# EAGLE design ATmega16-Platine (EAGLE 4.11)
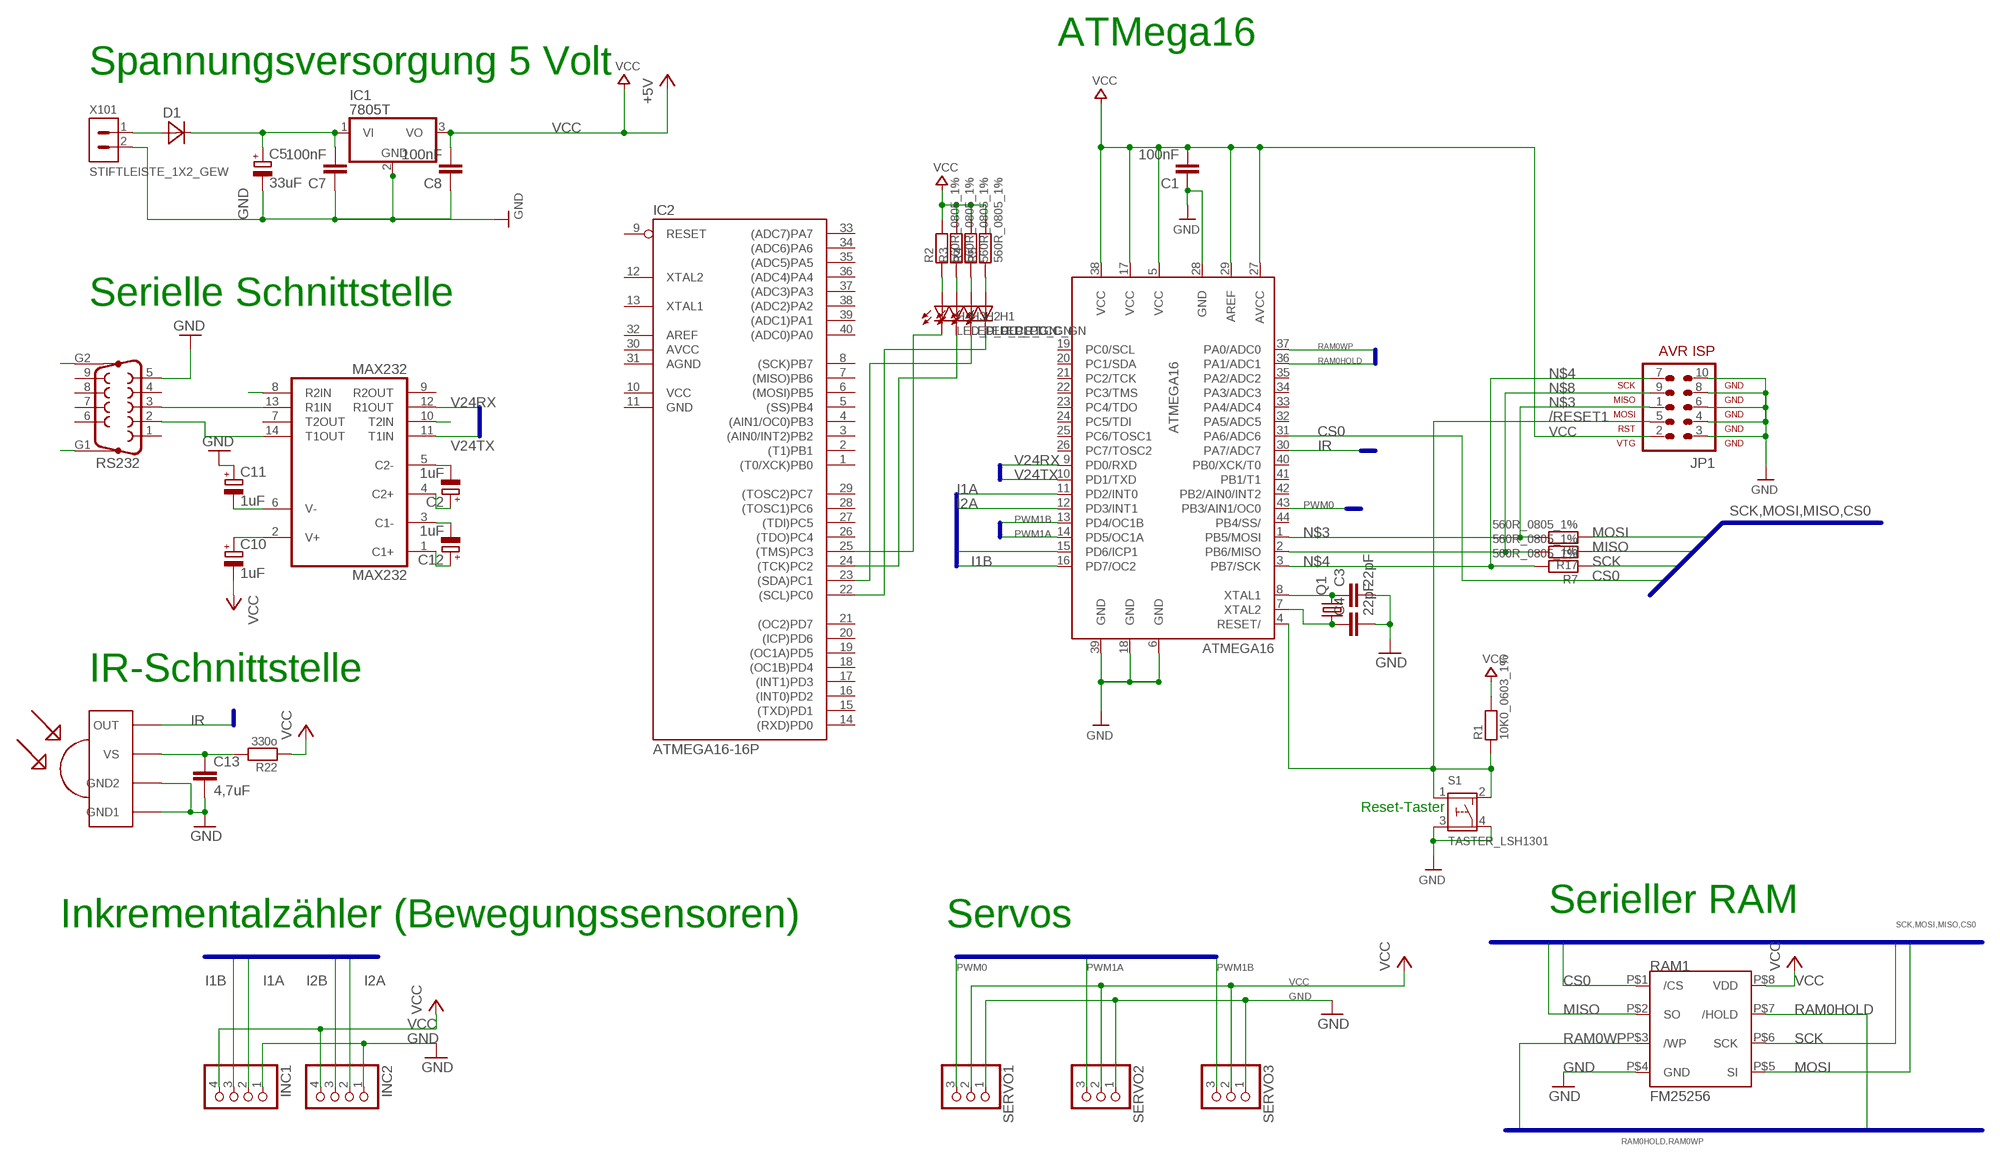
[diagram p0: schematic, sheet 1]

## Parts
ATMEGA16  ATMEGA16  [SQFP-S-10X10-44]
C1  100nF  C2.5/2  [C2.5-2]
C2  1uF  CPOL-EUE2.5-5  [E2,5-5]
C3  22pF  C2.5/2  [C2.5-2]
C4  22pF  C2.5/2  [C2.5-2]
C5  33uF  CPOL-EUE2.5-5  [E2,5-5]
C7  100nF  C2.5/2  [C2.5-2]
C8  100nF  C2.5/2  [C2.5-2]
C10  1uF  CPOL-EUE2.5-5  [E2,5-5]
C11  1uF  CPOL-EUE2.5-5  [E2,5-5]
C12  1uF  CPOL-EUE2.5-5  [E2,5-5]
C13  4,7uF  C-EU025-024X044  [C025-024X044]
D1  DIODE-10  [D-10]
H1  LED_PLCC_GN  [PLCC2]
H2  LED_PLCC_GN  [PLCC2]
H3  LED_PLCC_GN  [PLCC2]
H4  LED_PLCC_RT  [PLCC2]
IC1  7805T  [TO220H]
IC2  ATMEGA16-16P  [DIL40]
INC1  PINHD-1X4  [1X04]
INC2  PINHD-1X4  [1X04]
JP1  AVR-ISP-10  [AVR-ISP-10]
MAX232  MAX232  [DIL16]
Q1  CRYTALHC49S  [HC49/S]
R1  10K0_0603_1%  [R0603]
R2  560R_0805_1%  [R0805]
R3  560R_0805_1%  [R0805]
R4  560R_0805_1%  [R0805]
R5  560R_0805_1%  [R0805]
R6  560R_0805_1%  [R0805]
R7  560R_0805_1%  [R0805]
R17  560R_0805_1%  [R0805]
R22  330o  10K0_0603_1%  [R0603]
RAM1  FM25256  [EIAJ-SOIC-8]
RS232  F09HP  [F09HP]
S1  TASTER_LSH1301  [LSH1301]
SERVO1  PINHD-1X3  [1X03]
SERVO2  PINHD-1X3  [1X03]
SERVO3  PINHD-1X3  [1X03]
TSOP6236  TSOP6236  [TSOP62XX]
X101  STIFTLEISTE_1X2_GEW  [PFOSTENSTECKER_1X2_GEW]

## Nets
/RESET1: ATMEGA16.4(RESET/) JP1.5 R1.1 S1.1 S1.2
CS0: ATMEGA16.31(PA6/ADC6) RAM1.P$1(/CS)
GND: ATMEGA16.6(GND) ATMEGA16.18(GND) ATMEGA16.28(GND) ATMEGA16.39(GND) C1.1 C3.2 C4.2 C5.- C7.1 C8.1 C11.+ C13.2 IC1.2(GND) INC1.1 INC2.1 JP1.3 JP1.4 JP1.6 JP1.8 JP1.10 MAX232.8(R2IN) MAX232.10(T2IN) RAM1.P$4(GND) RS232.5 RS232.G1 RS232.G2 S1.3 S1.4 SERVO1.1 SERVO2.1 SERVO3.1 TSOP6236.GND1 TSOP6236.GND2 X101.2
I1A: ATMEGA16.11(PD2/INT0) INC1.2
I1B: ATMEGA16.16(PD7/OC2) INC1.3
I2A: ATMEGA16.12(PD3/INT1) INC2.2
I2B: INC2.3
IR: ATMEGA16.30(PA7/ADC7) TSOP6236.OUT
MISO: R17.1 RAM1.P$2(SO)
MOSI: R6.1 RAM1.P$5(SI)
N$1: ATMEGA16.8(XTAL1) C3.1 Q1.2
N$2: ATMEGA16.7(XTAL2) C4.1 Q1.1
N$3: ATMEGA16.1(PB5/MOSI) JP1.1 R6.2
N$4: ATMEGA16.3(PB7/SCK) JP1.7 R7.2
N$5: H4.K IC2.25((TMS)PC3)
N$6: ATMEGA16.15(PD6/ICP1)
N$8: ATMEGA16.2(PB6/MISO) JP1.9 R17.2
N$9: D1.1(A) X101.1
N$11: H1.A(A1) R5.1
N$12: C5.+ C7.2 D1.2(K) IC1.1(VI)
N$13: H2.A(A1) R4.1
N$19: H3.A(A1) R3.1
N$20: H4.A(A1) R2.1
N$21: H1.K IC2.22((SCL)PC0)
N$22: H2.K IC2.23((SDA)PC1)
N$23: H3.K IC2.24((TCK)PC2)
N$29: C2.- MAX232.5(C2-)
N$30: C2.+ MAX232.4(C2+)
N$31: C12.- MAX232.3(C1-)
N$32: C12.+ MAX232.1(C1+)
N$33: C11.- MAX232.6(V-)
N$34: C10.+ MAX232.2(V+)
N$40: MAX232.14(T1OUT) RS232.2
N$41: MAX232.13(R1IN) RS232.3
N$49: C13.1 R22.2 TSOP6236.VS
PWM0: ATMEGA16.43(PB3/AIN1/OC0) SERVO1.3
PWM1A: ATMEGA16.14(PD5/OC1A) SERVO2.3
PWM1B: ATMEGA16.13(PD4/OC1B) SERVO3.3
RAM0HOLD: ATMEGA16.36(PA1/ADC1) RAM1.P$7(/HOLD)
RAM0WP: ATMEGA16.37(PA0/ADC0) RAM1.P$3(/WP)
SCK: R7.1 RAM1.P$6(SCK)
V24RX: ATMEGA16.9(PD0/RXD) MAX232.12(R1OUT)
V24TX: ATMEGA16.10(PD1/TXD) MAX232.11(T1IN)
VCC: ATMEGA16.5(VCC) ATMEGA16.17(VCC) ATMEGA16.27(AVCC) ATMEGA16.29(AREF) ATMEGA16.38(VCC) C1.2 C8.2 C10.- IC1.3(VO) INC1.4 INC2.4 JP1.2 R1.2 R2.2 R3.2 R4.2 R5.2 R22.1 RAM1.P$8(VDD) SERVO1.2 SERVO2.2 SERVO3.2 ; supply symbol labelled +5V
Unconnected: ATMEGA16.19(PC0/SCL) ATMEGA16.20(PC1/SDA) ATMEGA16.21(PC2/TCK) ATMEGA16.22(PC3/TMS) ATMEGA16.23(PC4/TDO) ATMEGA16.24(PC5/TDI) ATMEGA16.25(PC6/TOSC1) ATMEGA16.26(PC7/TOSC2) ATMEGA16.32(PA5/ADC5) ATMEGA16.33(PA4/ADC4) ATMEGA16.34(PA3/ADC3) ATMEGA16.35(PA2/ADC2) ATMEGA16.40(PB0/XCK/T0) ATMEGA16.41(PB1/T1) ATMEGA16.42(PB2/AIN0/INT2) ATMEGA16.44(PB4/SS/) IC2.1((T0/XCK)PB0) IC2.2((T1)PB1) IC2.3((AIN0/INT2)PB2) IC2.4((AIN1/OC0)PB3) IC2.5((SS)PB4) IC2.6((MOSI)PB5) IC2.7((MISO)PB6) IC2.8((SCK)PB7) IC2.9(RESET) IC2.12(XTAL2) IC2.13(XTAL1) IC2.14((RXD)PD0) IC2.15((TXD)PD1) IC2.16((INT0)PD2) IC2.17((INT1)PD3) IC2.18((OC1B)PD4) IC2.19((OC1A)PD5) IC2.20((ICP)PD6) IC2.21((OC2)PD7) IC2.26((TDO)PC4) IC2.27((TDI)PC5) IC2.28((TOSC1)PC6) IC2.29((TOSC2)PC7) IC2.33((ADC7)PA7) IC2.34((ADC6)PA6) IC2.35((ADC5)PA5) IC2.36((ADC4)PA4) IC2.37((ADC3)PA3) IC2.38((ADC2)PA2) IC2.39((ADC1)PA1) IC2.40((ADC0)PA0) MAX232.7(T2OUT) MAX232.9(R2OUT) RS232.1 RS232.4 RS232.6 RS232.7 RS232.8 RS232.9

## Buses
SCK,MOSI,MISO,CS0
IR
PWM0,PWM1A,PWM1B
V24RX,V24TX
I1A,I1B,I2A,I2B
RAM0HOLD,RAM0WP

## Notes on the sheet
- ATMega16
- Spannungsversorgung 5 Volt
- Serielle Schnittstelle
- IR-Schnittstelle
- Reset-Taster
- Servos
- Serieller RAM
- Inkrementalzähler (Bewegungssensoren)

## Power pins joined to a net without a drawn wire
AGND: IC2.31(AGND)
AREF: IC2.32(AREF)
AVCC: IC2.30(AVCC)
GND: IC2.11(GND) MAX232.15(GND)
VCC: IC2.10(VCC) MAX232.16(VCC)

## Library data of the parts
ATMEGA16 = IntegrierteSchaltkreise:ATMEGA16: xxxxxxxx
C1 C3 C4 C7 C8 = capacitor-wima:C: CAPACITOR
C2 C5 C10-C12 = rcl:CPOL-EU: POLARIZED CAPACITOR, European symbol
C13 = rcl:C-EU: CAPACITOR, European symbol
D1 = discrete:DIODE-10
H1-H3 = LED:LED_PLCC_GN: 10800036
H4 = LED:LED_PLCC_RT: 10800053
IC1 = linear:78*: Positive VOLTAGE REGULATOR
IC2 = avr:ATMEGA16*P: MICROCONTROLLER 16 Kbytes FLASH 1 kbytes SRAM 512 bytes EEPROM USART 8-channel 10 bit ADC
INC1 INC2 = pinhead:PINHD-1X4: PIN HEADER
JP1 = atmel_3:AVR-ISP-10: AVR ISP-10 Serial Programming Header
MAX232 = maxim:MAX232: RS232 TRANSEIVER
Q1 = crystal:CRYTAL: CRYSTAL
R1 R22 = Widerstände:10K0_0603_1%: 10000534
R2-R7 R17 = Widerstände:560R_0805_1%: 10000417
RAM1 = ramtron25xx:FM25256
RS232 = con-subd:F09HP: SUB-D
S1 = Schalter_Taster:TASTER_LSH1301: 11100014
SERVO1-SERVO3 = pinhead:PINHD-1X3: PIN HEADER
TSOP6236 = tsop_2:TSOP6236
X101 = Stecker_Klemmen:STIFTLEISTE_1X2_GEW: 20900248

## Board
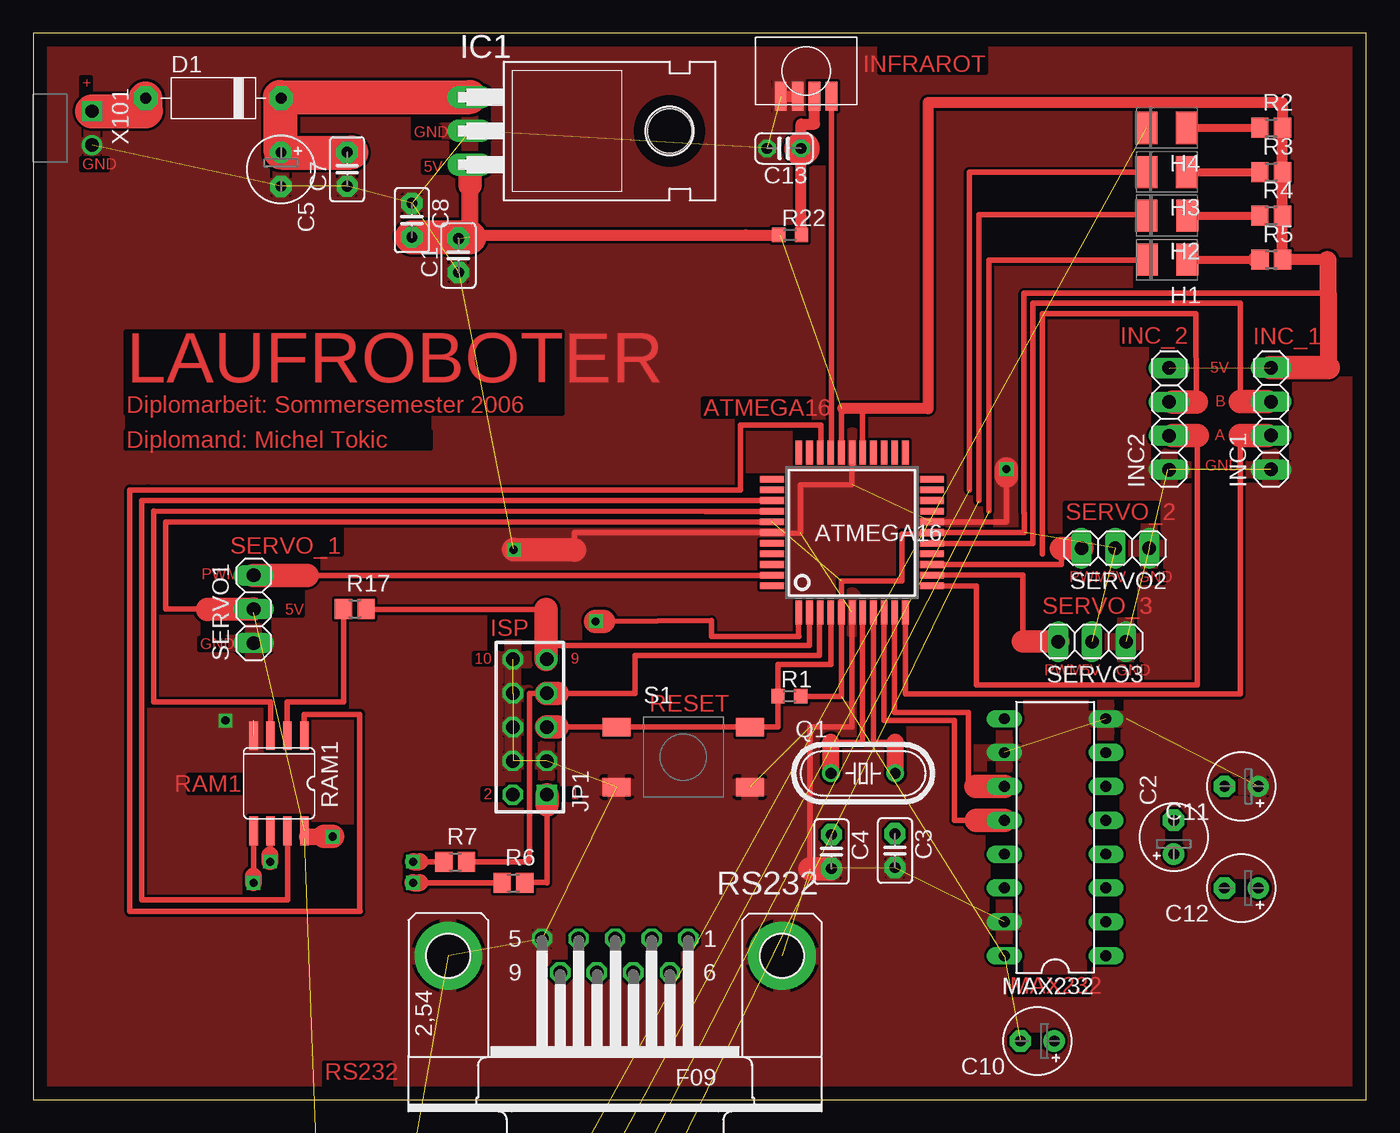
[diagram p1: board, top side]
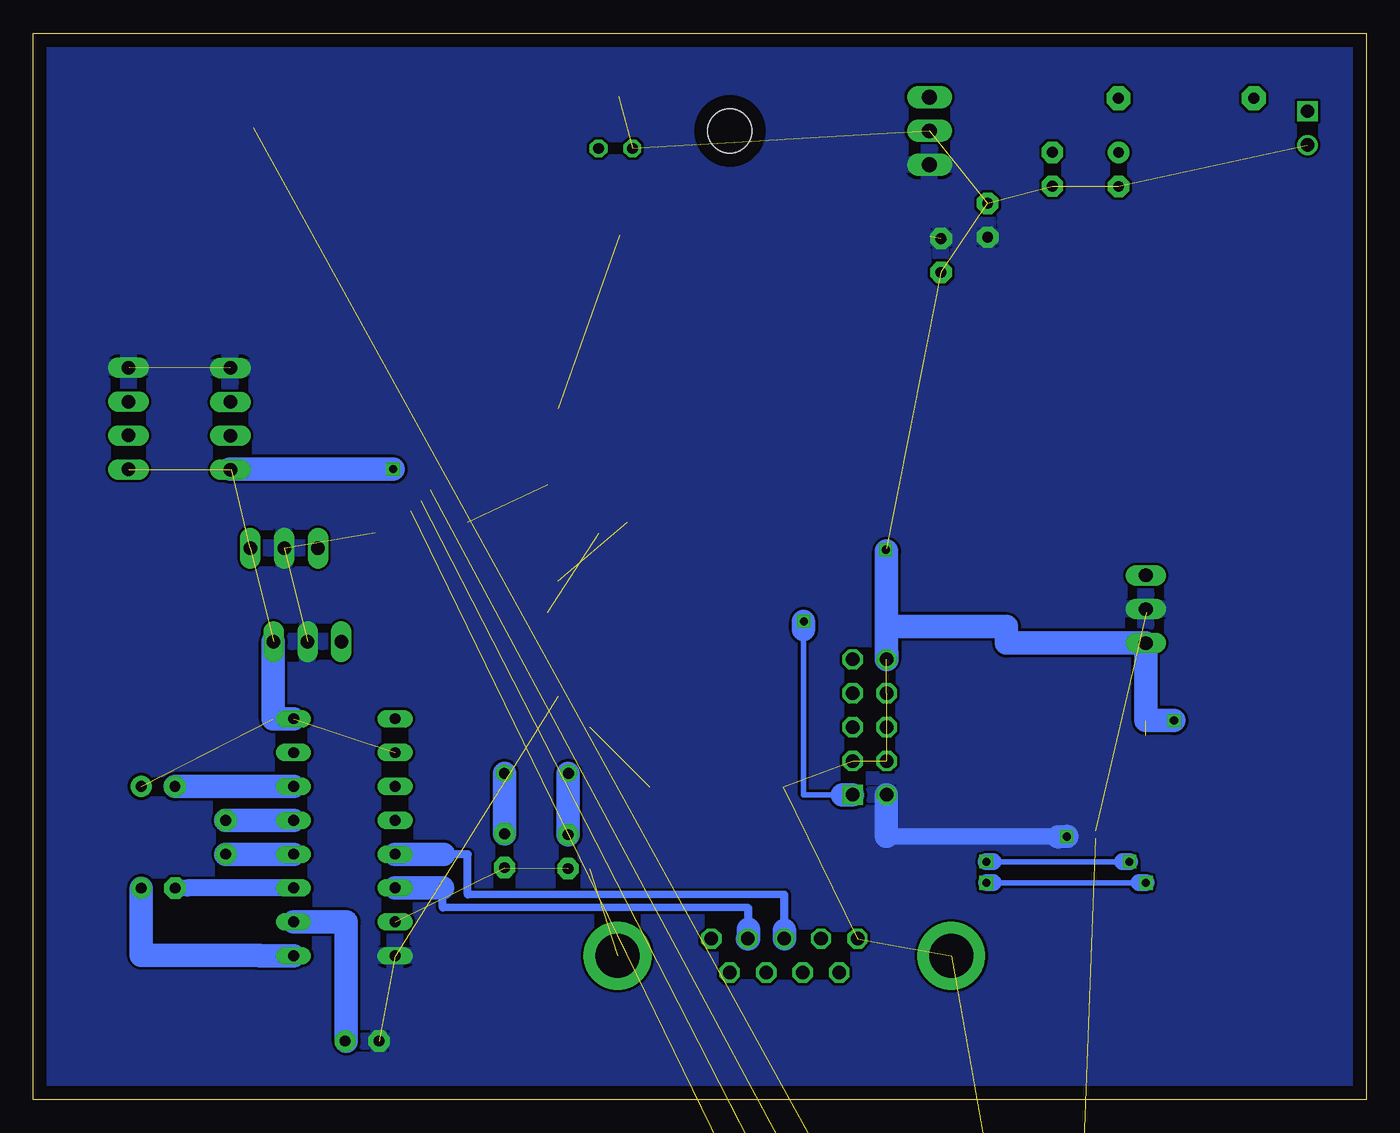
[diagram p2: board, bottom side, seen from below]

Size 100 x 80 mm. Coordinates in mm from the lower left corner, seen from the top.
Outline: 0,0 100,0 100,80 0,80 0,0
Copper layers (1*16): Top 0.035mm / dielectric 1.5mm / Bottom 0.035mm
Design rules "default": minimum track width 10mil, minimum drill 24mil, track to track 8mil, track to pad 8mil, pad to pad 8mil, via to via 8mil, smd to smd 8mil, copper to edge 40mil, drill to drill 8mil, minimum pad ring 10mil, minimum via ring 8mil, stop-mask expansion 4mil, vias tented up to drill 0mil, thermal gap 10mil

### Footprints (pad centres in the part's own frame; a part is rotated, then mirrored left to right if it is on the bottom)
SQFP-S-10X10-44 = smd 0.5 x 1.8: 1 -4,-6; 2 -3.2,-6; 3 -2.4,-6; 4 -1.6,-6; 5 -0.8,-6; 6 0,-6; 7 0.8,-6; 8 1.6,-6; 9 2.4,-6; 10 3.2,-6; 11 4,-6; 23 4,6; 24 3.2,6; 25 2.4,6; 26 1.6,6; 27 0.8,6; 28 0,6; 29 -0.8,6; 30 -1.6,6; 31 -2.4,6; 32 -3.2,6; 33 -4,6 | smd 1.8 x 0.5: 12 6,-4; 13 6,-3.2; 14 6,-2.4; 15 6,-1.6; 16 6,-0.8; 17 6,0; 18 6,0.8; 19 6,1.6; 20 6,2.4; 21 6,3.2; 22 6,4; 34 -6,4; 35 -6,3.2; 36 -6,2.4; 37 -6,1.6; 38 -6,0.8; 39 -6,0; 40 -6,-0.8; 41 -6,-1.6; 42 -6,-2.4; 43 -6,-3.2; 44 -6,-4
C2.5-2 = drill 0.813 pad 1.6 octagon: 1 -1.27,0; 2 1.27,0
E2,5-5 = drill 0.813 pad 1.6 round: + -1.27,0 | drill 0.813 pad 1.6 octagon: - 1.27,0
C025-024X044 = drill 0.813 octagon: 1 -1.27,0; 2 1.27,0
D-10 = drill 0.813 pad 1.778 octagon: 1 -5.08,0; 2 5.08,0
PLCC2 = smd 1.651 x 2.413: A 1.524,0; K -1.524,0
TO220H = drill 1.118 long: 1 -2.54,-10.16; 2 0,-10.16; 3 2.54,-10.16 | hole 3.302: 0,4.826
DIL40 = drill 0.813 long: 1 -24.13,-7.62; 2 -21.59,-7.62; 3 -19.05,-7.62; 4 -16.51,-7.62; 5 -13.97,-7.62; 6 -11.43,-7.62; 7 -8.89,-7.62; 8 -6.35,-7.62; 9 -3.81,-7.62; 10 -1.27,-7.62; 11 1.27,-7.62; 12 3.81,-7.62; 13 6.35,-7.62; 14 8.89,-7.62; 15 11.43,-7.62; 16 13.97,-7.62; 17 16.51,-7.62; 18 19.05,-7.62; 19 21.59,-7.62; 20 24.13,-7.62; 21 24.13,7.62; 22 21.59,7.62; 23 19.05,7.62; 24 16.51,7.62; 25 13.97,7.62; 26 11.43,7.62; 27 8.89,7.62; 28 6.35,7.62; 29 3.81,7.62; 30 1.27,7.62; 31 -1.27,7.62; 32 -3.81,7.62; 33 -6.35,7.62; 34 -8.89,7.62; 35 -11.43,7.62; 36 -13.97,7.62; 37 -16.51,7.62; 38 -19.05,7.62; 39 -21.59,7.62; 40 -24.13,7.62
1X04 = drill 1.016 long: 1 -3.81,0; 2 -1.27,0; 3 1.27,0; 4 3.81,0
AVR-ISP-10 = drill 1.016 square: 1 -5.08,-1.27 | drill 1.016 octagon: 2 -5.08,1.27; 3 -2.54,-1.27; 4 -2.54,1.27; 5 0,-1.27; 6 0,1.27; 7 2.54,-1.27; 8 2.54,1.27; 9 5.08,-1.27; 10 5.08,1.27
DIL16 = drill 0.813 long: 1 -8.89,-3.81; 2 -6.35,-3.81; 3 -3.81,-3.81; 4 -1.27,-3.81; 5 1.27,-3.81; 6 3.81,-3.81; 7 6.35,-3.81; 8 8.89,-3.81; 9 8.89,3.81; 10 6.35,3.81; 11 3.81,3.81; 12 1.27,3.81; 13 -1.27,3.81; 14 -3.81,3.81; 15 -6.35,3.81; 16 -8.89,3.81
HC49/S = drill 0.813 round: 1 -2.413,0; 2 2.413,0
R0603 = smd 1 x 1.1: 1 -0.85,0; 2 0.85,0
R0805 = smd 1.3 x 1.5: 1 -0.85,0; 2 0.85,0
EIAJ-SOIC-8 = smd 0.65 x 2.15: P$1 -1.905,-3.576; P$2 -0.635,-3.576; P$3 0.635,-3.576; P$4 1.905,-3.576; P$5 1.905,3.576; P$6 0.635,3.576; P$7 -0.635,3.576; P$8 -1.905,3.576
F09HP = drill 1.016 octagon: 1 -5.486,-1.27; 2 -2.743,-1.27; 3 0,-1.27; 4 2.743,-1.27; 5 5.486,-1.27; 6 -4.115,1.27; 7 -1.372,1.27; 8 1.372,1.27; 9 4.115,1.27 | drill 3.302 pad 5.08 round: G1 -12.522,0; G2 12.522,0
LSH1301 = smd 2.1 x 1.4: 1 -5,2.25; 2 5,2.25; 3 -5,-2.25; 4 5,-2.25
1X03 = drill 1.016 long: 1 -2.54,0; 2 0,0; 3 2.54,0
TSOP62XX = smd 0.889 x 2.184: GND1 -8.255,1.905; GND2 -6.985,1.905; OUT -4.445,1.905; VS -5.715,1.905
PFOSTENSTECKER_1X2_GEW = drill 1 square: 1 -1.27,0 | drill 1 round: 2 1.27,0

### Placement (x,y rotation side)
ATMEGA16  61.43,42.54 0 top
C1  31.89,63.33 90 top
C2  85.56,19.68 90 top
C3  64.65,18.67 270 top
C4  59.88,18.6 270 top
C5  18.58,69.79 270 top
C7  23.54,69.8 90 top
C8  28.4,65.98 270 top
C10  75.33,4.38 180 top
C11  90.64,23.49 180 top
C12  90.64,15.86 180 top
C13  56.32,71.36 180 top
D1  13.51,75.13 0 top
H1  85.05,63.01 0 top
H2  85.04,66.32 0 top
H3  85.04,69.59 0 top
H4  85.04,72.9 0 top
IC1  42.92,72.68 270 top
IC2  not placed on the board
INC1  92.86,51.09 90 top
INC2  85.22,51.08 90 top
JP1  37.25,27.94 90 top
MAX232  76.67,19.68 90 top
Q1  62.25,24.47 0 top
R1  56.72,30.26 0 top
R2  92.87,72.9 0 top
R3  92.87,69.59 0 top
R4  92.86,66.32 0 top
R5  92.88,63.02 0 top
R6  36.02,16.25 0 top
R7  31.66,17.83 0 top
R17  24.12,36.82 0 top
R22  56.78,64.87 0 top
RAM1  18.43,23.73 180 top
RS232  43.65,10.79 180 top
S1  48.77,25.69 0 top
SERVO1  16.53,36.79 90 top
SERVO2  81.17,41.37 180 top
SERVO3  79.43,34.36 180 top
TSOP6236  64.33,73.37 0 top
X101  4.4,72.89 270 top

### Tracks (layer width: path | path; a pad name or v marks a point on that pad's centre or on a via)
/RESET1
  Top 0.406: 55.88,30.26 55.88,32.64 59.83,32.64 ATMEGA16.4 | ATMEGA16.4 | 39.28,27.94 S1.1 | 43.88,27.94 S1.2 55.85,27.94 55.85,30.26 R1.1
  Top 0.61: R1.1 55.88,30.26 | S1.1 43.88,27.94
  Top 1.778: JP1.5 39.28,27.94
CS0
  Top 0.406: RAM1.P$1 20.33,28.89 24.48,28.89 24.48,14.11 24.51,14.11 7.25,14.11 7.24,45.74 8.61,45.74 53.04,45.73 53.04,50.59 59.08,50.59 59.1,48.43 59.02,48.43 ATMEGA16.31
GND  (via drill 0.61)  (28 unrouted)
  Top 0.406: ATMEGA16.6 61.42,36.54 61.42,27.97 58.28,27.97 58.28,17.31 | C4.2 59.83,17.33 59.83,17.31 59.83,17.28 | 40.62,41.24 40.62,42.54 55.28,42.54 | 55.28,42.54 ATMEGA16.39 | ATMEGA16.28 61.42,46.13 57.57,46.11 57.57,42.5 55.28,42.49 55.28,42.54 | 55.28,42.54 55.28,42.59 | 55.28,42.54 | ATMEGA16.18 73.01,43.34 73,46.8 | v73,47.3 v73.01,47.3 | INC2.1 85.12,47.27
  Top 0.813: TSOP6236.GND2 | TSOP6236.GND1 TSOP6236.GND2 | TSOP6236.GND2
  Top 1.778: 58.28,17.31 59.83,17.31 | v36.04,41.25 40.62,41.24 | 73,46.8 v73,47.3
  Bottom 0.254: 16.54,33.66 15.71,33.65 SERVO1.1
  Bottom 0.406: 16.51,28.43 16.53,28.43 | 35.99,33.01 35.96,38.22 35.98,38.22 35.98,41.35 v36.04,41.25 35.99,41.15 36.09,41.28 | JP1.10 35.99,33.02 | 85.22,47.3 INC2.1
  Bottom 1.27: INC1.1 92.85,47.3 | INC1.1 | INC1.1 92.85,47.27 | 82,34.36 SERVO3.1 | 35.98,35.49 35.98,34.26 | 35.97,33.02 JP1.10
  Bottom 1.778: MAX232.8 82,28.57 82,34.36 | SERVO1.1 26.98,34.25 26.98,35.49 35.98,35.49 | 35.98,34.26 35.97,33.02 | v14.42,28.43 16.51,28.43 | 16.53,28.43 16.54,33.66 16.54,34.13 | 35.99,33.02 35.99,41.15 | v73.01,47.3 85.22,47.3
  pour Top: 0.47,79.32 99.39,79.32 99.39,0.75 0.72,0.75 0.72,79.07
I1A
  Top 0.406: ATMEGA16.11 65.44,30.43 90.55,30.43 90.55,49.83 | 92.6,49.83
  Top 1.27: INC1.2 92.85,49.82 92.85,49.83 92.6,49.83
  Top 1.778: 90.55,49.83 92.6,49.83
I1B
  Top 0.406: 67.16,41.74 67.16,41.78 | ATMEGA16.16 67.16,41.74 | 90.56,59.77 75.01,59.77 75.01,43.39 75,43.39 75,41.73 67.16,41.73 67.16,41.74 | 90.56,59.77 89.37,59.77 | 90.56,59.77 90.56,52.36 | 92.85,52.36 | 92.6,52.36 92.85,52.36
  Top 1.27: INC1.3 92.85,52.36
  Top 1.778: 90.56,52.36 92.6,52.36
I2A
  Top 0.406: ATMEGA16.12 70.77,38.54 70.77,31.11 87.33,31.11 87.33,49.82 | 85.18,49.81 INC2.2 | 85.48,49.82
  Top 1.27: 85.48,49.82 85.18,49.82 85.18,49.81
  Top 1.778: 87.33,49.82 85.48,49.82
I2B
  Top 0.406: 75.71,40.94 75.71,42.6 75.71,58.97 87.23,58.96 87.25,52.35 | 85.24,52.35 | 85.48,52.35
  Top 1.27: 85.24,52.35 INC2.3 | 85.48,52.35 85.24,52.35
  Top 1.778: 87.25,52.35 85.48,52.35
IR
  Top 0.406: ATMEGA16.30 59.8,48.54 59.79,48.56 59.89,48.66 TSOP6236.OUT
MISO
  Top 0.406: 19.05,27.28 | RAM1.P$2 19.05,27.28 | R17.1 23.26,30.89 23.26,29.82 19.05,29.82 19.05,27.28
MOSI  (via drill 0.61)
  Top 0.406: RAM1.P$5 16.53,16.77 | v16.52,16.26 v16.53,16.26 | R6.1 35.02,16.25 35.02,16.26 29.01,16.25 29.01,16.26
  Top 1.27: v16.53,16.26 16.53,16.77 | v28.49,16.26 29.01,16.26
  Bottom 0.406: 17.05,16.26 17.05,16.25 27.98,16.25 27.98,16.26
  Bottom 1.27: v16.52,16.26 17.05,16.26 | 27.98,16.26 v28.49,16.26
N$1
  Top 0.406: ATMEGA16.8 63.02,27.65 63.02,26.8 64.67,26.8
  Top 1.27: Q1.2 64.67,26.8
  Bottom 1.27: C3.1 | 64.65,24.47 Q1.2
  Bottom 1.778: C3.1 64.65,24.47
N$2
  Top 0.406: ATMEGA16.7 62.2,36.54 62.2,26.79 59.83,26.8
  Top 1.27: Q1.1 59.83,26.8
  Bottom 1.27: C4.1 | 59.88,24.47 Q1.1
  Bottom 1.778: C4.1 59.88,24.47
N$3  (via drill 0.61)
  Top 0.406: 42.8,35.88 50.87,35.93 50.87,34.73 57.45,34.73 57.41,34.77 57.41,36.52 ATMEGA16.1 | 38.56,22.86 38.56,22.88 | 38.56,22.86 JP1.1 | 38.54,22.1 38.54,16.27 38.52,16.28 37.06,16.28 37.01,16.25 R6.2 | 38.54,22.86 38.56,22.86
  Top 1.27: 38.54,22.1 | 38.54,22.86
  Top 1.778: v42.19,35.88 42.8,35.88 | 38.54,22.1 38.54,22.86
  Bottom 0.406: JP1.1 | 39.04,22.85 40.28,22.86 42.21,22.86 42.21,35.27 | 42.21,35.88 v42.19,35.88
  Bottom 1.27: 39.28,22.85 39.04,22.85
  Bottom 1.778: JP1.1 39.04,22.85 39.28,22.85 | 42.21,35.27 42.21,35.88
N$4
  Top 0.406: R7.2 37.13,17.83 37.13,18.06 37.23,18.06 37.23,30.47 37.72,30.47 38.27,30.47 JP1.7 | 38.48,30.48 JP1.7 38.57,30.48 | ATMEGA16.3 58.99,36.54 58.99,33.33 45.16,33.33 45.16,30.48 40.07,30.48 39.24,30.48 38.57,30.48 | 38.57,30.48
  Top 1.778: JP1.7 39.28,30.47 | 39.28,30.47 39.3,30.47 | 39.28,30.47 39.28,30.48 | 39.28,30.48 38.57,30.48 | 39.28,30.48 39.28,30.49
N$5  (1 unrouted)
N$8
  Top 0.406: R17.2 24.92,36.76 38.48,36.76 | 38.48,33.02 38.53,33.03 JP1.9 | 38.52,34.07 58.24,34.07 ATMEGA16.2
  Top 1.27: JP1.9 38.52,34.07
  Top 1.778: 38.48,36.76 38.48,33.02
N$9
  Top 2.54: 8.39,74.16 8.44,74.17 D1.1 | X101.1 8.39,74.16 | 8.39,74.16
N$11
  Top 0.61: H1.A 91.78,63.01
  Top 1.27: 91.78,63.02 | 91.78,63.02 R5.1 | 91.78,63.01 91.78,63.02
N$12
  Top 1.27: 18.57,70.89 C5.+ | 18.57,75.13 D1.2 18.52,75.13 18.52,75.22 18.52,75.23 | 23.86,71.07 23.86,71.11 | 23.86,71.07 C7.2 | 23.86,71.06 23.86,71.07
  Top 2.54: C5.+ 18.57,75.13 | C5.+ 23.86,71.06 | 18.52,75.22 IC1.1
N$13
  Top 0.61: R4.1 92.19,66.32 H2.A
N$19
  Top 0.61: 91.95,69.59 | 91.95,69.59 R3.1 | H3.A 91.95,69.59
N$20
  Top 0.61: 92.05,72.9 | 92.05,72.9 R2.1 | H4.A 92.05,72.9
N$21  (1 unrouted)
  Top 0.406: 71.69,44.14 71.69,62.98 83.29,62.98 83.29,63.01 | 83.29,63.01 83.29,63.02 | 83.29,63.01 H1.K
N$22  (1 unrouted)
  Top 0.406: 70.92,44.94 70.92,66.39 83.35,66.39 83.35,66.38 | 83.35,66.38 83.35,66.32 | 83.35,66.38 H2.K
N$23  (1 unrouted)
  Top 0.406: 70.23,45.74 70.23,69.57 83.3,69.59 | 83.3,69.59 | 83.3,69.59 H3.K
N$29
  Bottom 1.778: MAX232.5 C2.-
N$30
  Bottom 1.778: MAX232.4 C2.+
N$31
  Bottom 1.27: MAX232.3 88.45,15.87 C12.-
N$32
  Bottom 1.27: 83.02,10.79 83.02,10.83
  Bottom 1.778: MAX232.1 83.02,10.79 | 83.02,10.83 91.9,10.83 C12.+
N$33
  Bottom 1.778: MAX232.6 C11.-
N$34
  Bottom 1.27: 76.52,4.26 76.52,4.38 C10.+
  Bottom 1.778: MAX232.2 76.52,13.33 76.52,4.38
N$40
  Bottom 0.61: 69.29,15.87 69.29,14.41 46.35,14.37 46.35,12.78 | RS232.2 46.35,12.06
  Bottom 1.778: 69.29,15.87 MAX232.14 | RS232.2 46.41,12.06 | 46.35,12.06 46.35,12.78
N$41
  Bottom 0.61: 69.22,18.41 67.41,18.41 67.41,15.38 43.65,15.37 43.65,12.69 | RS232.3
  Bottom 1.27: 69.22,18.41 69.22,18.4
  Bottom 1.778: 69.22,18.4 MAX232.13 | RS232.3 43.65,12.69
N$49
  Top 0.406: 57.59,71.34 57.6,71.34 | 57.58,71.39 57.6,71.39
  Top 0.813: TSOP6236.VS 58.62,73.18 57.59,73.18 57.6,71.82 | 57.59,71.34 C13.1 57.6,71.39 | 57.6,66.23 57.6,66.2 | R22.2 57.6,66.23 | 57.6,66.23 57.58,70.9
  Top 1.27: 57.6,71.34 57.6,71.82 | 57.58,70.9 57.58,71.39
  Top 2.54: 57.59,71.34 57.71,71.36
PWM0
  Top 0.406: 55.3,39.33 55.31,39.34 ATMEGA16.43 | 55.3,39.33 | 55.3,39.33 55.22,39.33 55.21,39.34 55.2,39.33 20.54,39.33
  Top 1.778: SERVO1.3 20.54,39.33
PWM1A
  Top 0.406: ATMEGA16.14 77.15,40.14 77.15,41.35
  Top 1.27: SERVO2.3 78.68,41.37 78.68,41.38
  Top 1.778: 77.15,41.35 78.68,41.38
PWM1B
  Top 0.406: ATMEGA16.13 74.23,39.34 74.23,34.36
  Top 1.676: 74.23,34.36 SERVO3.3
RAM0HOLD
  Top 0.406: RAM1.P$7 19.09,20.13 19.09,14.99 8.12,14.99 8.12,44.94 49.39,44.94 49.28,44.94 55.21,44.94 | 55.21,44.94 55.21,44.99 | 55.21,44.94 ATMEGA16.36
RAM0WP
  Top 0.406: RAM1.P$3 17.81,27.31 17.8,27.31 17.8,29.81 | 17.8,29.81 17.8,29.82 | ATMEGA16.37 56.07,44.12 51.05,44.13 50.45,44.12 9.02,44.17 9.03,44.12 9.03,29.82 | 9.03,29.82 | 17.8,29.81 17.8,29.82 9.03,29.82
SCK  (via drill 0.61)
  Top 0.406: RAM1.P$6 17.77,20.12 17.77,18.35 | v17.77,17.84 | 30.5,17.83 30.5,17.82 | 30.5,17.83 R7.1 | 29,17.84 30.5,17.84 30.5,17.83
  Top 1.27: v17.77,17.84 17.77,18.35 | v28.49,17.84 29,17.84
  Bottom 0.406: 18.29,17.84 27.98,17.84
  Bottom 1.27: v17.77,17.84 18.29,17.84 | 27.98,17.84 v28.49,17.84
V24RX
  Top 0.406: ATMEGA16.9 63.81,36.54 63.83,28.9 63.82,28.44 69.11,28.44 69.11,20.95 70.74,20.95
  Top 1.778: 70.74,20.95 MAX232.12
V24TX
  Top 0.406: ATMEGA16.10 64.6,36.54 64.61,29.05 70.16,29.05 70.16,23.42 70.73,23.51
  Top 1.778: 70.73,23.51 MAX232.11
VCC  (via drill 0.61)  (10 unrouted)
  Top 0.406: 56,64.87 R22.1 | 32.76,68.61 32.77,68.61 32.77,68.6 | 32.76,64.74 32.76,64.86 | ATMEGA16.27 62.2,48.54 | 67.62,42.54 74.34,42.54 74.34,44 74.33,43.99 74.33,60.49 97.15,60.49 | 67.62,42.54 ATMEGA16.17 | IC1.3 32.79,70.06 32.79,70.1 32.77,70.1 | ATMEGA16.27 62.25,48.54 | ATMEGA16.27 62.22,51.83 60.71,51.85 60.64,51.85 ATMEGA16.29 | 93.72,72.81 93.74,72.81 | ATMEGA16.29 | 67.13,51.84 67.13,51.82 | ATMEGA16.29 60.64,48.25 | ATMEGA16.38 9.95,43.34 9.95,36.8 13.13,36.8 13.08,36.76 | 16.51,36.79 16.51,36.53 | 16.51,36.79 SERVO1.2 | 16.51,36.8 16.51,36.79 | R1.2 60.64,30.26 60.64,30.27 60.65,30.27 60.64,36.54 ATMEGA16.5 60.62,38.92 65.19,38.92 65.19,42.43 67.62,42.43 67.62,42.54 | 20.34,19.73 20.34,19.6 | 20.34,19.73 20.56,19.73 | RAM1.P$8 20.34,19.73
  Top 0.61: 93.72,69.43 R3.2 93.72,69.55 | 93.72,62.99 R5.2 | 93.72,66.32 R4.2 | R2.2 93.72,72.81
  Top 0.813: 32.76,64.86 53.46,64.86 56,64.87 | R3.2 93.72,66.32 R5.2 | 97.02,63.02 R5.2 | R3.2 93.72,72.81 | 60.71,51.85 67.09,51.85 67.13,51.84 67.13,74.8 93.74,74.8 93.74,72.81
  Top 1.27: R5.2 | 97.15,54.93 97.15,60.49 97.14,60.49 97.14,63.02 97.02,63.02 | 32.77,68.61 32.76,64.74 32.71,64.74 32.71,64.71 | INC1.4 92.8,54.9 92.8,54.93 | 20.56,19.73 21.82,19.72 21.82,19.73
  Top 1.778: 32.77,68.61 32.77,70.1 | 13.08,36.76 16.51,36.8 | 97.15,54.93 92.8,54.93 | 21.82,19.73 v22.46,19.73
  Top 2.54: C8.2 32.71,64.71
  Bottom 1.27: INC1.4 92.85,54.89 | MAX232.16 72.8,10.79 | 23.11,19.72 23.11,19.73 23.37,19.73 23.37,19.72 35.98,19.73
  Bottom 1.778: 35.98,19.73 JP1.2 | v22.46,19.73 23.11,19.72
  pour Bottom: 0.57,79.31 99.26,79.31 99.26,0.42 0.57,0.42

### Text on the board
Top: INFRAROT | + | GND | GND | 5V | INC_2 | INC_1 | 5V | LAUFROBOTER | Diplomarbeit: Sommersemester 2006 | ATMEGA16 | B | A | Diplomand: Michel Tokic | GND | SERVO_2 | SERVO_1 | PWM | PWM | 5V | GND | 5V | SERVO_3 | ISP | GND | 10 | 9 | PWM | 5V | GND | RESET | RAM1 | 2 | 1 | MAX232 | RS232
